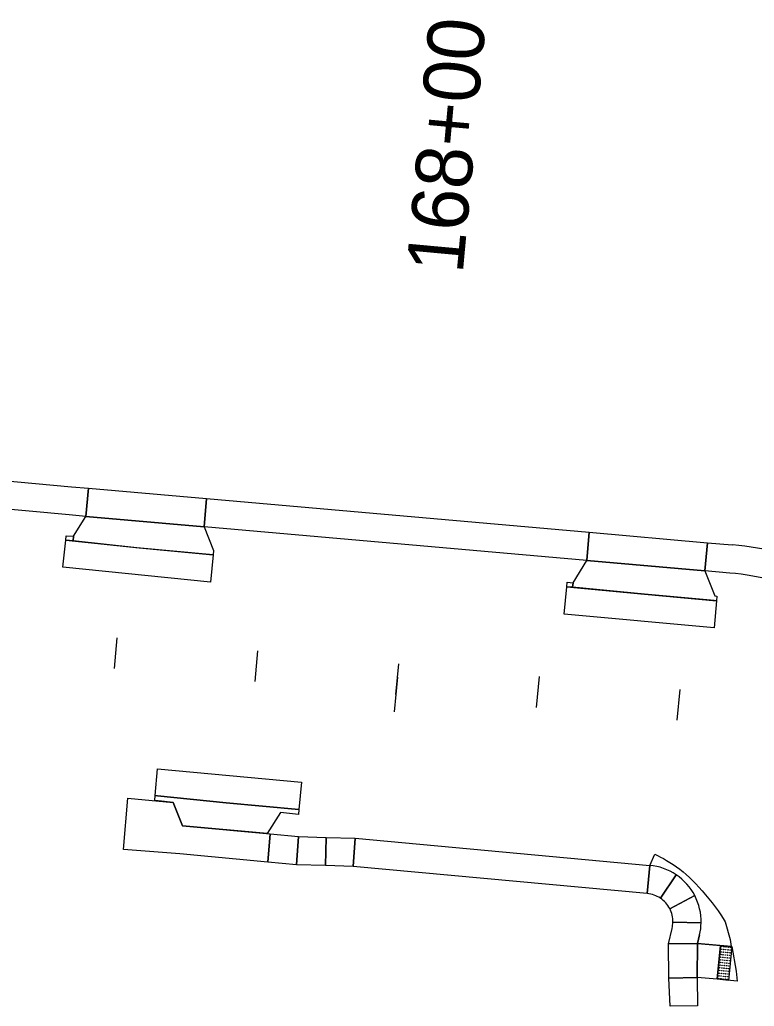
# Model space of a CAD drawing. Extents: x 20499216 to 20505321, y 7953487 to 7960535.
# Drawn here: x 20500446.4 to 20500576.4, y 7953944.7 to 7954119.1 of the extents above; entities that cross this region are included whole.
import ezdxf

# ---------------------------------------------------------------- set-up
doc = ezdxf.new("R2010")
doc.units = 0
for name, color, linetype in [('Drainage', 7, 'Continuous'), ('EXT_CU', 7, 'Continuous'), ('EXT_RR', 7, 'Continuous'), ('NamedBoundary', 7, 'Continuous'), ('Roadways', 7, 'Continuous'), ('Safety', 7, 'Continuous')]:
    doc.layers.add(name, color=color, linetype=linetype)

msp = doc.modelspace()

# ---------------------------------------------------------------- linework, layer by layer
at = {"layer": 'Drainage'}
for points in [[(20500566.31, 7953949.76), (20500566.37, 7953955.78), (20500570.42, 7953955.4), (20500569.86, 7953949.43)], [(20500570.42, 7953955.4), (20500572.41, 7953955.22), (20500571.86, 7953949.25), (20500569.86, 7953949.43)], [(20500570.42, 7953955.4), (20500572.41, 7953955.22), (20500573.22, 7953950.85), (20500573.36, 7953949.11), (20500569.86, 7953949.43)], [(20500561.31, 7953949.66), (20500566.31, 7953949.76), (20500566.34, 7953944.76), (20500561.5, 7953944.67)]]:
    msp.add_lwpolyline(points, close=True, dxfattribs=at)
at = {"layer": 'EXT_CU'}
for p, q in [((20500557.92, 7953969.58), (20500558.83, 7953971.56)), ((20500557.46, 7953964.6), (20500557.92, 7953969.58)), ((20500559.79, 7953963.77), (20500562.58, 7953967.92)), ((20500562.58, 7953967.92), (20500559.79, 7953963.77)), ((20500561.44, 7953961.92), (20500565.88, 7953964.23)), ((20500565.88, 7953964.23), (20500561.44, 7953961.92)), ((20500562, 7953959.51), (20500567, 7953959.41)), ((20500567, 7953959.41), (20500562, 7953959.51)), ((20500569.86, 7953949.43), (20500570.42, 7953955.4)), ((20500570.42, 7953955.4), (20500572.41, 7953955.22)), ((20500572.41, 7953955.22), (20500571.86, 7953949.25)), ((20500571.86, 7953949.25), (20500569.86, 7953949.43))]:
    msp.add_line(p, q, dxfattribs=at)
for points in [[(20500455.16, 7954031.55), (20500387.57, 7954037.77), (20500388.03, 7954042.75), (20500455.61, 7954036.53), (20500458.58, 7954036.27), (20500458.14, 7954031.29)], [(20500479.5, 7954034.43), (20500479.07, 7954029.45), (20500458.14, 7954031.29), (20500458.58, 7954036.27)], [(20500547.19, 7954028.47), (20500546.75, 7954023.49), (20500479.07, 7954029.45), (20500479.5, 7954034.43)], [(20500568.11, 7954026.63), (20500567.67, 7954021.65), (20500546.75, 7954023.49), (20500547.19, 7954028.47)], [(20500490.76, 7953975.14), (20500490.31, 7953970.16), (20500474.76, 7953971.59), (20500464.8, 7953972.41), (20500465.56, 7953981.45), (20500473.6, 7953980.72), (20500475.22, 7953976.57)], [(20500495.74, 7953974.69), (20500495.43, 7953969.69), (20500490.31, 7953970.16), (20500490.76, 7953975.14)], [(20500495.43, 7953969.69), (20500495.74, 7953974.69), (20500500.68, 7953974.52), (20500500.51, 7953969.53)], [(20500505.76, 7953974.36), (20500505.44, 7953969.36), (20500500.51, 7953969.53), (20500500.68, 7953974.52)], [(20500505.76, 7953974.36), (20500557.92, 7953969.58), (20500557.46, 7953964.6), (20500505.44, 7953969.36)]]:
    msp.add_lwpolyline(points, close=True, dxfattribs=at)
for points in [[(20500572.09, 7954021.26), (20500567.67, 7954021.65), (20500568.11, 7954026.63), (20500572.52, 7954026.24)], [(20500571.23, 7953959.61), (20500572.12, 7953956.45), (20500572.32, 7953955.23), (20500566.37, 7953955.78), (20500566.73, 7953957.27)], [(20500566.73, 7953957.27), (20500566.37, 7953955.78), (20500561.2, 7953955.7), (20500561.87, 7953958.44)]]:
    msp.add_lwpolyline(points, dxfattribs=at)
for centre, radius, start, end in [((20500567.79, 7953972.46), 53.99, 75.4533, 84.9678), ((20500567.79, 7953972.46), 48.99, 75.4533, 84.9678), ((20500557, 7953959.62), 10, 56.1166, 84.7645), ((20500557, 7953959.62), 10, 56.1166, 84.7645), ((20500557, 7953959.62), 10, 27.4687, 56.1166), ((20500557, 7953959.62), 10, 27.4687, 56.1166), ((20500557, 7953959.62), 5, 56.1166, 84.7645), ((20500557, 7953959.62), 5, 27.4687, 56.1166), ((20500557, 7953959.62), 10, 358.8208, 27.4687), ((20500557, 7953959.62), 10, 358.8208, 27.4687), ((20500557, 7953959.62), 5, 358.8208, 27.4687), ((20500557, 7953959.62), 5, 346.4397, 358.8208), ((20500557, 7953959.62), 10, 346.4397, 358.8208), ((20500557, 7953959.62), 10, 346.4397, 358.8208)]:
    msp.add_arc(centre, radius, start, end, dxfattribs=at)
for centre, major_axis in [((20500570.54, 7953954.28), (-0.0043, -0.0448)), ((20500570.54, 7953954.28), (-0.0022, -0.0224)), ((20500570.58, 7953954.75), (-0.0043, -0.0448)), ((20500570.58, 7953954.75), (-0.0022, -0.0224)), ((20500570.63, 7953955.21), (-0.0043, -0.0448)), ((20500570.63, 7953955.21), (-0.0022, -0.0224)), ((20500570.93, 7953954.24), (-0.0043, -0.0448)), ((20500570.93, 7953954.24), (-0.0022, -0.0224)), ((20500570.97, 7953954.71), (-0.0043, -0.0448)), ((20500570.97, 7953954.71), (-0.0022, -0.0224)), ((20500571.02, 7953955.18), (-0.0043, -0.0448)), ((20500571.02, 7953955.18), (-0.0022, -0.0224)), ((20500571.32, 7953954.21), (-0.0043, -0.0448)), ((20500571.32, 7953954.21), (-0.0022, -0.0224)), ((20500571.36, 7953954.67), (-0.0043, -0.0448)), ((20500571.36, 7953954.67), (-0.0022, -0.0224)), ((20500571.41, 7953955.14), (-0.0043, -0.0448)), ((20500571.41, 7953955.14), (-0.0022, -0.0224)), ((20500571.71, 7953954.17), (-0.0043, -0.0448)), ((20500571.71, 7953954.17), (-0.0022, -0.0224)), ((20500571.75, 7953954.64), (-0.0043, -0.0448)), ((20500571.75, 7953954.64), (-0.0022, -0.0224)), ((20500571.8, 7953955.11), (-0.0043, -0.0448)), ((20500571.8, 7953955.11), (-0.0022, -0.0224)), ((20500572.1, 7953954.13), (-0.0043, -0.0448)), ((20500572.1, 7953954.13), (-0.0022, -0.0224)), ((20500572.14, 7953954.6), (-0.0043, -0.0448)), ((20500572.14, 7953954.6), (-0.0022, -0.0224)), ((20500572.19, 7953955.07), (-0.0043, -0.0448)), ((20500572.19, 7953955.07), (-0.0022, -0.0224)), ((20500570.37, 7953952.41), (-0.0043, -0.0448)), ((20500570.37, 7953952.41), (-0.0022, -0.0224)), ((20500570.41, 7953952.87), (-0.0043, -0.0448)), ((20500570.41, 7953952.87), (-0.0022, -0.0224)), ((20500570.45, 7953953.34), (-0.0043, -0.0448)), ((20500570.45, 7953953.34), (-0.0022, -0.0224)), ((20500570.5, 7953953.81), (-0.0043, -0.0448)), ((20500570.5, 7953953.81), (-0.0022, -0.0224)), ((20500570.76, 7953952.37), (-0.0043, -0.0448)), ((20500570.76, 7953952.37), (-0.0022, -0.0224)), ((20500570.8, 7953952.84), (-0.0043, -0.0448)), ((20500570.8, 7953952.84), (-0.0022, -0.0224)), ((20500570.84, 7953953.31), (-0.0043, -0.0448)), ((20500570.84, 7953953.31), (-0.0022, -0.0224)), ((20500570.89, 7953953.77), (-0.0043, -0.0448)), ((20500570.89, 7953953.77), (-0.0022, -0.0224)), ((20500571.15, 7953952.33), (-0.0043, -0.0448)), ((20500571.15, 7953952.33), (-0.0022, -0.0224)), ((20500571.19, 7953952.8), (-0.0043, -0.0448)), ((20500571.19, 7953952.8), (-0.0022, -0.0224)), ((20500571.23, 7953953.27), (-0.0043, -0.0448)), ((20500571.23, 7953953.27), (-0.0022, -0.0224)), ((20500571.28, 7953953.74), (-0.0043, -0.0448)), ((20500571.28, 7953953.74), (-0.0022, -0.0224)), ((20500571.54, 7953952.3), (-0.0043, -0.0448)), ((20500571.54, 7953952.3), (-0.0022, -0.0224)), ((20500571.58, 7953952.77), (-0.0043, -0.0448)), ((20500571.58, 7953952.77), (-0.0022, -0.0224)), ((20500571.62, 7953953.23), (-0.0043, -0.0448)), ((20500571.62, 7953953.23), (-0.0022, -0.0224)), ((20500571.67, 7953953.7), (-0.0043, -0.0448)), ((20500571.67, 7953953.7), (-0.0022, -0.0224)), ((20500571.93, 7953952.26), (-0.0043, -0.0448)), ((20500571.93, 7953952.26), (-0.0022, -0.0224)), ((20500571.97, 7953952.73), (-0.0043, -0.0448)), ((20500571.97, 7953952.73), (-0.0022, -0.0224)), ((20500572.01, 7953953.2), (-0.0043, -0.0448)), ((20500572.01, 7953953.2), (-0.0022, -0.0224)), ((20500572.06, 7953953.67), (-0.0043, -0.0448)), ((20500572.06, 7953953.67), (-0.0022, -0.0224)), ((20500570.19, 7953950.51), (-0.0043, -0.0448)), ((20500570.19, 7953950.51), (-0.0022, -0.0224)), ((20500570.23, 7953951), (-0.0043, -0.0448)), ((20500570.23, 7953951), (-0.0022, -0.0224)), ((20500570.28, 7953951.47), (-0.0043, -0.0448)), ((20500570.28, 7953951.47), (-0.0022, -0.0224)), ((20500570.32, 7953951.94), (-0.0043, -0.0448)), ((20500570.32, 7953951.94), (-0.0022, -0.0224)), ((20500570.58, 7953950.47), (-0.0043, -0.0448)), ((20500570.58, 7953950.47), (-0.0022, -0.0224)), ((20500570.62, 7953950.97), (-0.0043, -0.0448)), ((20500570.62, 7953950.97), (-0.0022, -0.0224)), ((20500570.67, 7953951.43), (-0.0043, -0.0448)), ((20500570.67, 7953951.43), (-0.0022, -0.0224)), ((20500570.71, 7953951.9), (-0.0043, -0.0448)), ((20500570.71, 7953951.9), (-0.0022, -0.0224)), ((20500570.97, 7953950.44), (-0.0043, -0.0448)), ((20500570.97, 7953950.44), (-0.0022, -0.0224)), ((20500571.01, 7953950.93), (-0.0043, -0.0448)), ((20500571.01, 7953950.93), (-0.0022, -0.0224)), ((20500571.06, 7953951.4), (-0.0043, -0.0448)), ((20500571.06, 7953951.4), (-0.0022, -0.0224)), ((20500571.1, 7953951.87), (-0.0043, -0.0448)), ((20500571.1, 7953951.87), (-0.0022, -0.0224)), ((20500571.36, 7953950.4), (-0.0043, -0.0448)), ((20500571.36, 7953950.4), (-0.0022, -0.0224)), ((20500571.4, 7953950.9), (-0.0043, -0.0448)), ((20500571.4, 7953950.9), (-0.0022, -0.0224)), ((20500571.45, 7953951.36), (-0.0043, -0.0448)), ((20500571.45, 7953951.36), (-0.0022, -0.0224)), ((20500571.49, 7953951.83), (-0.0043, -0.0448)), ((20500571.49, 7953951.83), (-0.0022, -0.0224)), ((20500571.79, 7953950.86), (-0.0043, -0.0448)), ((20500571.79, 7953950.86), (-0.0022, -0.0224)), ((20500571.84, 7953951.33), (-0.0043, -0.0448)), ((20500571.84, 7953951.33), (-0.0022, -0.0224)), ((20500571.88, 7953951.8), (-0.0043, -0.0448)), ((20500571.88, 7953951.8), (-0.0022, -0.0224)), ((20500570.1, 7953949.57), (-0.0043, -0.0448)), ((20500570.1, 7953949.57), (-0.0022, -0.0224)), ((20500570.14, 7953950.04), (-0.0043, -0.0448)), ((20500570.14, 7953950.04), (-0.0022, -0.0224)), ((20500570.49, 7953949.54), (-0.0043, -0.0448)), ((20500570.49, 7953949.54), (-0.0022, -0.0224)), ((20500570.53, 7953950.01), (-0.0043, -0.0448)), ((20500570.53, 7953950.01), (-0.0022, -0.0224)), ((20500570.88, 7953949.5), (-0.0043, -0.0448)), ((20500570.88, 7953949.5), (-0.0022, -0.0224)), ((20500570.92, 7953949.97), (-0.0043, -0.0448)), ((20500570.92, 7953949.97), (-0.0022, -0.0224)), ((20500571.27, 7953949.47), (-0.0043, -0.0448)), ((20500571.27, 7953949.47), (-0.0022, -0.0224)), ((20500571.31, 7953949.93), (-0.0043, -0.0448)), ((20500571.31, 7953949.93), (-0.0022, -0.0224)), ((20500571.66, 7953949.43), (-0.0043, -0.0448)), ((20500571.66, 7953949.43), (-0.0022, -0.0224)), ((20500571.71, 7953949.9), (-0.0043, -0.0448)), ((20500571.71, 7953949.9), (-0.0022, -0.0224)), ((20500571.75, 7953950.37), (-0.0043, -0.0448)), ((20500571.75, 7953950.37), (-0.0022, -0.0224))]:
    msp.add_ellipse(centre, major_axis=major_axis, ratio=0.833333, dxfattribs=at)
msp.add_open_spline([(20500558.83, 7953971.56), (20500559.28, 7953971.34), (20500562.84, 7953969.52), (20500567.02, 7953965.53), (20500570.47, 7953961.08), (20500571.23, 7953959.61)], degree=3, dxfattribs=at)
at = {"layer": 'EXT_RR'}
for p, q in [((20500463.2, 7954004.36), (20500463.69, 7954009.79)), ((20500488.09, 7954002.08), (20500488.59, 7954007.51)), ((20500513.27, 7954002.85), (20500512.71, 7953996.75)), ((20500537.88, 7953997.52), (20500538.38, 7954002.96)), ((20500562.78, 7953995.24), (20500563.28, 7954000.68))]:
    msp.add_line(p, q, dxfattribs=at)
at = {"layer": 'NamedBoundary'}
for points in [[(20500479.07, 7954029.45), (20500480.71, 7954025.23), (20500480.64, 7954024.46), (20500467.15, 7954025.75), (20500455.89, 7954026.94), (20500455.96, 7954027.77), (20500458.14, 7954031.29)], [(20500454.64, 7954027.86), (20500455.96, 7954027.77), (20500455.96, 7954027.77), (20500455.89, 7954026.94), (20500454.57, 7954027.08)], [(20500454.57, 7954027.08), (20500467.54, 7954025.71), (20500480.64, 7954024.46), (20500480.18, 7954019.66), (20500454.07, 7954022.3)], [(20500567.67, 7954021.65), (20500569.4, 7954017.21), (20500569.77, 7954017.16), (20500569.7, 7954016.38), (20500569.33, 7954016.43), (20500556.98, 7954017.51), (20500544.26, 7954018.74), (20500544.33, 7954019.56), (20500546.75, 7954023.49)], [(20500569.28, 7954011.59), (20500542.78, 7954014), (20500543.22, 7954018.85), (20500556.98, 7954017.51), (20500569.7, 7954016.38)], [(20500543.3, 7954019.65), (20500544.33, 7954019.56), (20500544.33, 7954019.56), (20500544.26, 7954018.74), (20500543.22, 7954018.85)], [(20500495.81, 7953979.43), (20500482.95, 7953980.64), (20500470.79, 7953981.89), (20500470.39, 7953981.92), (20500470.79, 7953986.65), (20500470.81, 7953986.65), (20500496.27, 7953984.28)], [(20500490.24, 7953975.19), (20500475.22, 7953976.57), (20500473.6, 7953980.72), (20500471.51, 7953980.94), (20500470.32, 7953981.05), (20500470.39, 7953981.92), (20500470.79, 7953981.89), (20500482.95, 7953980.64), (20500495.81, 7953979.43), (20500495.74, 7953978.6), (20500492.56, 7953978.94)]]:
    msp.add_lwpolyline(points, close=True, dxfattribs=at)
at = {"layer": 'Roadways'}
msp.add_lwpolyline([(20500566.31, 7953949.76), (20500561.31, 7953949.66), (20500561.2, 7953955.7), (20500566.37, 7953955.78)], close=True, dxfattribs=at)
at = {"layer": 'Safety'}
msp.add_line((20500512.99, 7953999.8), (20500513.49, 7954005.24), dxfattribs=at)

# ---------------------------------------------------------------- texts
at = {"layer": 'EXT_RR'}
msp.add_text('168+00', height=10.02, rotation=84.7714, dxfattribs=at).set_placement((20500524.81, 7954074.03))

doc.saveas('drawing.dxf')
